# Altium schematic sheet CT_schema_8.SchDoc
size 278 x 170 mm
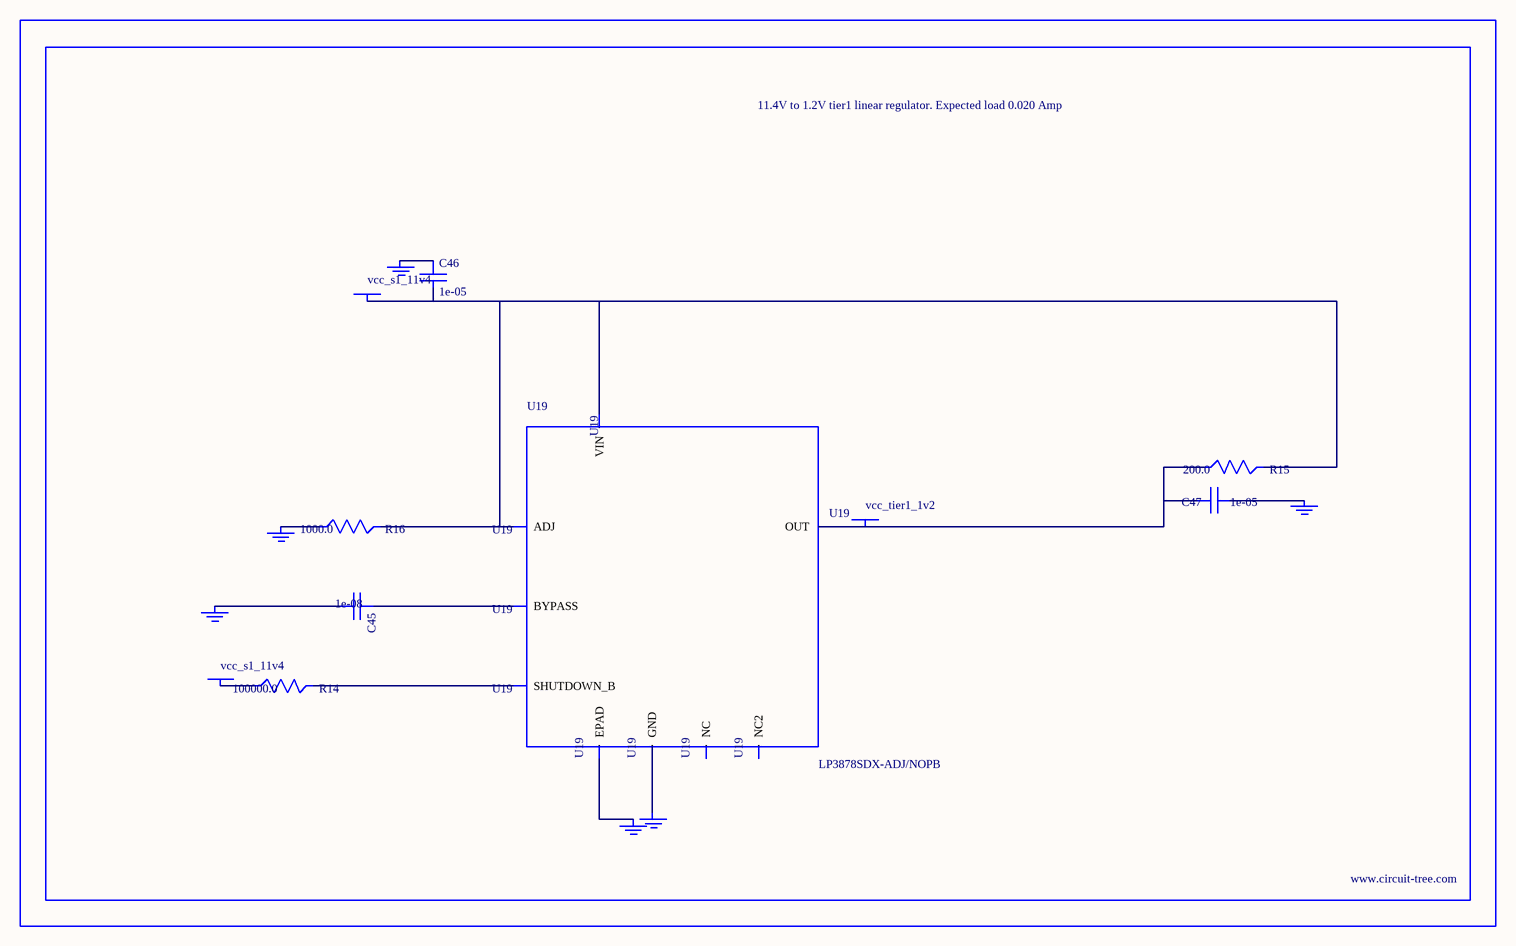
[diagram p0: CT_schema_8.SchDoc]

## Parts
BORDER7  (no value)
C45  1e-08  [C0402]
C46  1e-05  [C1210]
C47  1e-05  [C0805]
GND_INSTANCE_7_0  (no value)
GND_INSTANCE_7_1  (no value)
GND_INSTANCE_7_2  (no value)
GND_INSTANCE_7_3  (no value)
GND_INSTANCE_7_4  (no value)
GND_INSTANCE_7_5  (no value)
POWER_INSTANCE_7_0  vcc_s1_11v4
POWER_INSTANCE_7_1  vcc_s1_11v4
POWER_INSTANCE_7_2  vcc_tier1_1v2
R14  100000.0  [R0603]
R15  200.0  [R0603]
R16  1000.0  [R0603]
U19  LP3878SDX-ADJ/NOPB  [WSON-8]

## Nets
NetC45_1: C45.1 U19.1(BYPASS)
NetC45_2: C45.2 GND_INSTANCE_7_0.0(GND)
NetC46_1: C46.1 GND_INSTANCE_7_1.0(GND)
NetC46_2: C46.2 POWER_INSTANCE_7_0.0(PWR) R15.2 R16.2 U19.4(VIN) U19.6(ADJ)
NetC47_1: C47.1 GND_INSTANCE_7_2.0(GND)
NetC47_2: C47.2 POWER_INSTANCE_7_2.0(PWR) R15.1 U19.5(OUT)
NetGND_INSTANCE_7_3_0: GND_INSTANCE_7_3.0(GND) R16.1
NetGND_INSTANCE_7_4_0: GND_INSTANCE_7_4.0(GND) U19.PAD(EPAD)
NetGND_INSTANCE_7_5_0: GND_INSTANCE_7_5.0(GND) U19.3(GND)
NetPOWER_INSTANCE_7_1_0: POWER_INSTANCE_7_1.0(PWR) R14.1
NetR14_2: R14.2 U19.8(SHUTDOWN_B)

Not connected (* = marked no-connect by the designer): U19 2(NC) 7(NC2)

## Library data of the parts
BORDER7 = BORDER_PAGE7
C45 = C0402C103K3RAC
C46 = C1210C106K5PACTU
C47 = GRM219R60J106ME19D
GND_INSTANCE_7_0-GND_INSTANCE_7_5 = GND
POWER_INSTANCE_7_0-POWER_INSTANCE_7_2 = PWR
R14 = RC0603JR-07100KL
R15 = RC0603JR-07200RL
R16 = RC0603JR-071KL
